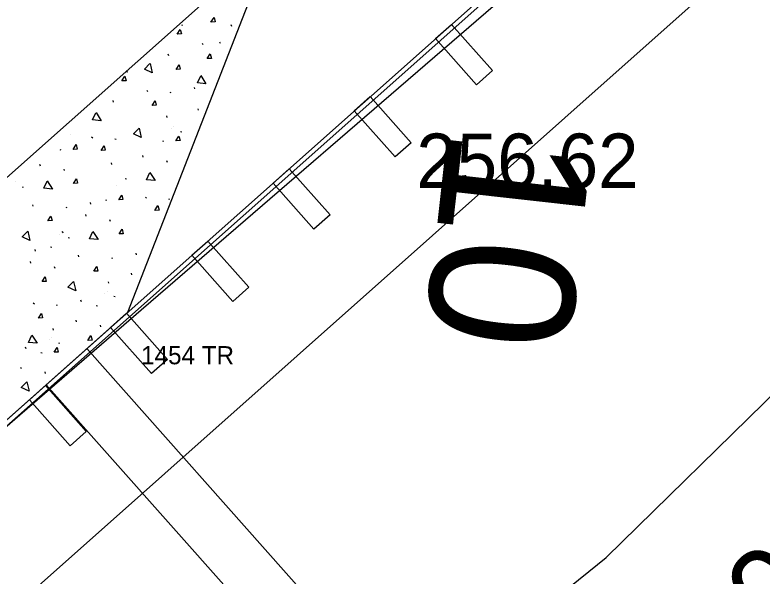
# Model space of a CAD drawing. Extents: x 49683 to 58852, y 49525 to 54803.
# Drawn here: x 55410.01 to 55451.25, y 53131.47 to 53162.44 of the extents above; entities that cross this region are included whole.
import ezdxf

# ---------------------------------------------------------------- set-up
doc = ezdxf.new("R2010")
doc.units = 0
for name, color, linetype in [('Level 11', 7, 'Continuous'), ('Level 13', 7, 'Continuous'), ('Level 15', 7, 'Continuous'), ('Level 18', 7, 'Continuous'), ('Level 20', 7, 'Continuous'), ('Level 21', 7, 'Continuous'), ('Level 27', 7, 'Continuous'), ('Level 32', 7, 'Continuous'), ('Level 48', 7, 'Continuous'), ('Level 61', 7, 'Continuous'), ('Level 8', 7, 'Continuous')]:
    doc.layers.add(name, color=color, linetype=linetype)

msp = doc.modelspace()

# ---------------------------------------------------------------- linework, layer by layer
at = {"layer": 'Level 11'}
for p, q in [((55416.975, 53146.156), (55479.228, 53199.919)), ((55223.521, 52979.087), (55416.975, 53146.156))]:
    msp.add_line(p, q, dxfattribs=at)
at = {"layer": 'Level 13'}
msp.add_line((55456.917, 53171.479), (55307.435, 53038.607), dxfattribs=at)
at = {"layer": 'Level 15'}
for p, q in [((55424.231, 53166.509), (55400.369, 53145.299)), ((55424.231, 53166.509), (55416.223, 53146.012)), ((55416.223, 53146.012), (55404.292, 53135.407)), ((55413.981, 53144.019), (55432.128, 53123.603)), ((55411.739, 53142.026), (55429.886, 53121.61))]:
    msp.add_line(p, q, dxfattribs=at)
at = {"layer": 'Level 18'}
for p, q in [((55442.646, 53132.484), (55478.405, 53167.515)), ((55411.368, 53107.463), (55442.646, 53132.484))]:
    msp.add_line(p, q, dxfattribs=at)
at = {"layer": 'Level 20'}
msp.add_line((55400.369, 53145.299), (56158.823, 53819.476), dxfattribs=at)
at = {"layer": 'Level 27'}
for p, q in [((55388.385, 53121.267), (55489.26, 53210.933)), ((55388.551, 53121.08), (55489.426, 53210.747)), ((55433.23, 53161.129), (55434.113, 53161.914)), ((55434.113, 53161.914), (55436.372, 53159.372)), ((55435.488, 53158.587), (55433.23, 53161.129)), ((55436.372, 53159.372), (55435.488, 53158.587)), ((55428.745, 53157.142), (55429.629, 53157.928)), ((55429.629, 53157.928), (55431.887, 53155.386)), ((55431.004, 53154.601), (55428.745, 53157.142)), ((55431.887, 53155.386), (55431.004, 53154.601)), ((55424.261, 53153.156), (55425.144, 53153.941)), ((55425.144, 53153.941), (55427.403, 53151.4)), ((55426.519, 53150.615), (55424.261, 53153.156)), ((55427.403, 53151.4), (55426.519, 53150.615)), ((55419.776, 53149.17), (55420.66, 53149.955)), ((55420.66, 53149.955), (55422.918, 53147.414)), ((55422.035, 53146.629), (55419.776, 53149.17)), ((55422.918, 53147.414), (55422.035, 53146.629)), ((55415.292, 53145.184), (55416.175, 53145.969)), ((55416.175, 53145.969), (55418.434, 53143.428)), ((55417.55, 53142.642), (55415.292, 53145.184)), ((55418.434, 53143.428), (55417.55, 53142.642)), ((55410.807, 53141.198), (55411.691, 53141.983)), ((55411.691, 53141.983), (55413.949, 53139.441)), ((55413.066, 53138.656), (55410.807, 53141.198)), ((55413.949, 53139.441), (55413.066, 53138.656))]:
    msp.add_line(p, q, dxfattribs=at)
at = {"layer": 'Level 8'}
for p, q in [((55419.286, 53161.858), (55419.222, 53161.876)), ((55421.932, 53161.913), (55421.957, 53161.825)), ((55421.311, 53160.962), (55421.337, 53160.874)), ((55420.404, 53160.804), (55420.343, 53160.861)), ((55418.456, 53160.293), (55418.482, 53160.206)), ((55416.235, 53159.271), (55416.171, 53159.289)), ((55419.905, 53158.441), (55419.931, 53158.354)), ((55417.353, 53158.217), (55417.292, 53158.274)), ((55418.64, 53158.145), (55418.576, 53158.163)), ((55415.405, 53157.706), (55415.431, 53157.619)), ((55420.099, 53157.262), (55420.124, 53157.174)), ((55418.371, 53156.861), (55418.396, 53156.774)), ((55418.645, 53156.174), (55418.645, 53156.174)), ((55418.773, 53156.281), (55418.773, 53156.281)), ((55419.214, 53155.965), (55419.15, 53155.984)), ((55413.098, 53155.811), (55413.098, 53155.811)), ((55414.302, 53155.63), (55414.242, 53155.687)), ((55415.59, 53155.558), (55415.525, 53155.576)), ((55418.238, 53155.447), (55418.174, 53155.465)), ((55412.564, 53154.977), (55412.5, 53154.995)), ((55417.048, 53154.675), (55417.073, 53154.587)), ((55418.384, 53154.401), (55418.409, 53154.313)), ((55411.373, 53154.205), (55411.399, 53154.117)), ((55412.709, 53153.931), (55412.735, 53153.843)), ((55415.32, 53154.274), (55415.346, 53154.187)), ((55410.047, 53153.224), (55410.047, 53153.224)), ((55416.163, 53153.378), (55416.099, 53153.397)), ((55410.488, 53152.909), (55410.424, 53152.927)), ((55415.623, 53153.025), (55415.623, 53153.025)), ((55417.281, 53152.325), (55417.22, 53152.382)), ((55418.568, 53152.253), (55418.504, 53152.271)), ((55410.976, 53151.964), (55411.002, 53151.876)), ((55414.158, 53152.079), (55414.184, 53151.992)), ((55415.089, 53152.19), (55415.025, 53152.209)), ((55412.893, 53151.783), (55412.829, 53151.801)), ((55413.898, 53151.418), (55413.924, 53151.33)), ((55415.234, 53151.144), (55415.26, 53151.056)), ((55412.445, 53150.33), (55412.445, 53150.33)), ((55412.572, 53150.438), (55412.572, 53150.438)), ((55412.624, 53150.499), (55412.649, 53150.411)), ((55413.014, 53150.122), (55412.95, 53150.14)), ((55411.107, 53149.492), (55411.133, 53149.405)), ((55412.038, 53149.603), (55411.974, 53149.622)), ((55413.501, 53149.177), (55413.527, 53149.09)), ((55415.419, 53148.996), (55415.354, 53149.014)), ((55416.683, 53149.292), (55416.709, 53149.205)), ((55410.848, 53148.831), (55410.873, 53148.744)), ((55412.183, 53148.557), (55412.209, 53148.469)), ((55416.424, 53148.177), (55416.449, 53148.09)), ((55415.149, 53147.712), (55415.174, 53147.625)), ((55414.97, 53147.089), (55414.97, 53147.089)), ((55415.097, 53147.197), (55415.097, 53147.197)), ((55415.539, 53146.881), (55415.475, 53146.9)), ((55411.081, 53146.481), (55411.02, 53146.538)), ((55413.633, 53146.705), (55413.658, 53146.618)), ((55412.368, 53146.409), (55412.304, 53146.427)), ((55414.563, 53146.363), (55414.499, 53146.381)), ((55413.373, 53145.59), (55413.398, 53145.503)), ((55414.709, 53145.317), (55414.734, 53145.229)), ((55412.098, 53145.125), (55412.124, 53145.038)), ((55411.919, 53144.502), (55411.919, 53144.502)), ((55412.047, 53144.61), (55412.047, 53144.61)), ((55410.582, 53144.118), (55410.607, 53144.031)), ((55412.488, 53144.294), (55412.424, 53144.313)), ((55411.512, 53143.776), (55411.448, 53143.794)), ((55410.322, 53143.003), (55410.347, 53142.916)), ((55411.658, 53142.73), (55411.683, 53142.642))]:
    msp.add_line(p, q, dxfattribs=at)
for points in [[(55420.999, 53162.301), (55421.064, 53162.053), (55420.833, 53162.039), (55420.999, 53162.301)], [(55419.132, 53161.642), (55419.196, 53161.394), (55418.966, 53161.38), (55419.132, 53161.642)], [(55420.795, 53160.287), (55420.86, 53160.039), (55420.629, 53160.025), (55420.795, 53160.287)], [(55417.47, 53159.756), (55417.585, 53159.235), (55417.156, 53159.441), (55417.463, 53159.75)], [(55419.069, 53159.69), (55419.134, 53159.442), (55418.903, 53159.428), (55419.069, 53159.69)], [(55416.081, 53159.055), (55416.146, 53158.807), (55415.915, 53158.793), (55416.081, 53159.055)], [(55420.267, 53159.087), (55420.553, 53158.636), (55420.079, 53158.683), (55420.263, 53159.079)], [(55417.744, 53157.7), (55417.809, 53157.452), (55417.578, 53157.438), (55417.744, 53157.7)], [(55414.485, 53157.051), (55414.771, 53156.601), (55414.297, 53156.647), (55414.481, 53157.043)], [(55416.866, 53156.191), (55416.98, 53155.67), (55416.551, 53155.876), (55416.859, 53156.185)], [(55419.059, 53155.75), (55419.124, 53155.501), (55418.893, 53155.488), (55419.059, 53155.75)], [(55413.385, 53155.28), (55413.449, 53155.032), (55413.219, 53155.018), (55413.385, 53155.28)], [(55414.927, 53155.219), (55414.992, 53154.971), (55414.761, 53154.957), (55414.927, 53155.219)], [(55417.463, 53153.746), (55417.749, 53153.295), (55417.276, 53153.342), (55417.459, 53153.738)], [(55411.789, 53153.276), (55412.075, 53152.825), (55411.601, 53152.872), (55411.784, 53153.268)], [(55413.402, 53153.397), (55413.467, 53153.148), (55413.236, 53153.135), (55413.402, 53153.397)], [(55415.91, 53152.493), (55415.975, 53152.245), (55415.744, 53152.231), (55415.91, 53152.493)], [(55417.905, 53151.914), (55417.97, 53151.665), (55417.74, 53151.652), (55417.905, 53151.914)], [(55411.997, 53151.338), (55412.062, 53151.09), (55411.831, 53151.076), (55411.997, 53151.338)], [(55415.927, 53150.61), (55415.993, 53150.362), (55415.762, 53150.348), (55415.927, 53150.61)], [(55410.725, 53150.512), (55410.839, 53149.991), (55410.41, 53150.197), (55410.718, 53150.506)], [(55414.314, 53150.489), (55414.6, 53150.038), (55414.126, 53150.085), (55414.309, 53150.481)], [(55414.522, 53148.551), (55414.587, 53148.303), (55414.356, 53148.289), (55414.522, 53148.551)], [(55411.676, 53147.978), (55411.74, 53147.729), (55411.51, 53147.716), (55411.676, 53147.978)], [(55413.25, 53147.725), (55413.364, 53147.204), (55412.935, 53147.41), (55413.243, 53147.719)], [(55411.471, 53145.964), (55411.536, 53145.716), (55411.306, 53145.702), (55411.471, 53145.964)], [(55410.944, 53144.764), (55411.23, 53144.313), (55410.756, 53144.36), (55410.939, 53144.756)], [(55414.201, 53144.737), (55414.266, 53144.489), (55414.035, 53144.475), (55414.201, 53144.737)], [(55412.333, 53144.078), (55412.398, 53143.83), (55412.167, 53143.816), (55412.333, 53144.078)], [(55410.672, 53142.193), (55410.787, 53141.671), (55410.357, 53141.877), (55410.665, 53142.187)]]:
    msp.add_lwpolyline(points, dxfattribs=at)

# ---------------------------------------------------------------- texts
at = {"layer": 'Level 21'}
msp.add_text('10', height=8, rotation=263.6308, dxfattribs=at).set_placement((55433.934, 53156.359))
at = {"layer": 'Level 32'}
msp.add_text('256.62', height=3, dxfattribs=at).set_placement((55432.168, 53152.889))
at = {"layer": 'Level 48'}
msp.add_text("50'F", height=5, rotation=41.6334, dxfattribs=at).set_placement((55449.289, 53125.01))
at = {"layer": 'Level 61'}
msp.add_text('1454 TR', height=1, dxfattribs=at).set_placement((55416.975, 53143.156))

doc.saveas('drawing.dxf')
